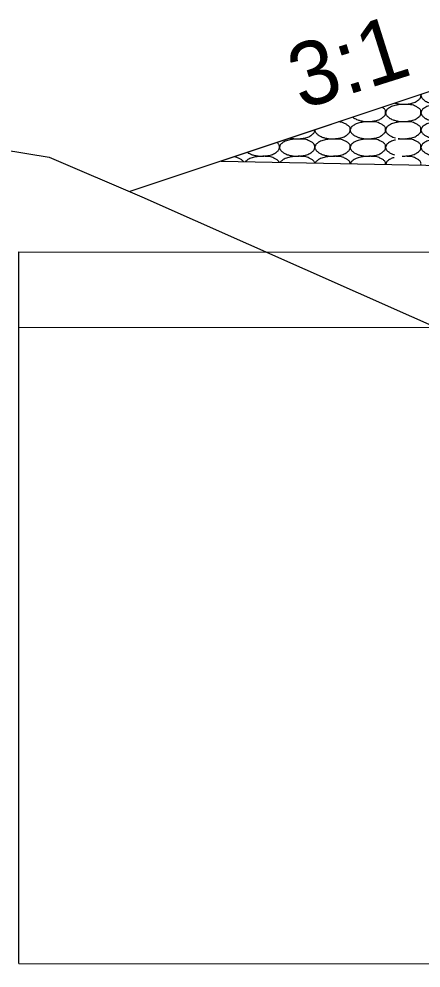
# Model space of a CAD drawing. Extents: x 2829243 to 2838161, y 467639 to 474695.
# Drawn here: x 2830390.5 to 2830428.5, y 467720.8 to 467810.3 of the extents above; entities that cross this region are included whole.
import ezdxf

# ---------------------------------------------------------------- set-up
doc = ezdxf.new("R2010")
doc.units = 0
for name, color, linetype in [('R_Draft', 7, 'Continuous'), ('R_Exist Surface', 7, 'Continuous'), ('R_Water', 7, 'Continuous')]:
    doc.layers.add(name, color=color, linetype=linetype)

msp = doc.modelspace()

# ---------------------------------------------------------------- linework, layer by layer
at = {"layer": 'R_Draft'}
for p, q in [((2830435.568, 467805.556), (2830409.614, 467796.905)), ((2830409.614, 467796.905), (2830674.829, 467791.601))]:
    msp.add_line(p, q, dxfattribs=at)
for points in [[(2830428.513, 467803.204), (2830428.511, 467803.2), (2830428.499, 467803.153), (2830428.456, 467803.078), (2830428.506, 467802.96), (2830428.554, 467802.853), (2830428.649, 467802.736), (2830428.772, 467802.663), (2830428.849, 467802.547), (2830428.983, 467802.521), (2830429.155, 467802.419), (2830429.466, 467802.337), (2830429.868, 467802.253), (2830430.342, 467802.26), (2830430.834, 467802.327), (2830431.282, 467802.448), (2830431.578, 467802.679), (2830431.788, 467802.859), (2830431.812, 467803.052), (2830431.815, 467803.219), (2830431.776, 467803.36), (2830431.694, 467803.457), (2830431.606, 467803.538), (2830431.476, 467803.595), (2830431.365, 467803.686), (2830431.202, 467803.745), (2830431.001, 467803.844), (2830430.754, 467803.857), (2830430.589, 467803.872), (2830430.529, 467803.876)], [(2830426.007, 467802.369), (2830426.031, 467802.363), (2830426.205, 467802.321), (2830426.529, 467802.253), (2830427.003, 467802.26), (2830427.495, 467802.327), (2830427.943, 467802.448), (2830428.239, 467802.679), (2830428.449, 467802.859), (2830428.471, 467803.046), (2830428.476, 467803.148), (2830428.472, 467803.191)], [(2830422.05, 467801.05), (2830422.067, 467801.037), (2830422.118, 467801.002), (2830422.171, 467800.916), (2830422.305, 467800.89), (2830422.476, 467800.788), (2830422.788, 467800.706), (2830423.19, 467800.622), (2830423.664, 467800.629), (2830424.155, 467800.696), (2830424.604, 467800.817), (2830424.9, 467801.048), (2830425.11, 467801.228), (2830425.133, 467801.422), (2830425.137, 467801.588), (2830425.097, 467801.729), (2830425.015, 467801.826), (2830424.927, 467801.907), (2830424.85, 467801.946), (2830424.811, 467801.97)], [(2830425.27, 467801.771), (2830425.239, 467801.744), (2830425.201, 467801.668), (2830425.169, 467801.551), (2830425.116, 467801.447), (2830425.167, 467801.329), (2830425.214, 467801.222), (2830425.31, 467801.105), (2830425.432, 467801.032), (2830425.51, 467800.916), (2830425.644, 467800.89), (2830425.816, 467800.788), (2830426.127, 467800.706), (2830426.529, 467800.622), (2830427.003, 467800.629), (2830427.495, 467800.696), (2830427.943, 467800.817), (2830428.239, 467801.048), (2830428.449, 467801.228), (2830428.472, 467801.422), (2830428.476, 467801.588), (2830428.436, 467801.729), (2830428.354, 467801.826), (2830428.266, 467801.907), (2830428.136, 467801.964), (2830428.025, 467802.055), (2830427.863, 467802.114), (2830427.661, 467802.213), (2830427.331, 467802.234), (2830426.98, 467802.257), (2830426.627, 467802.225), (2830426.355, 467802.221), (2830426.12, 467802.155), (2830425.894, 467802.118), (2830425.678, 467802.041), (2830425.482, 467801.934), (2830425.352, 467801.83), (2830425.262, 467801.77), (2830425.24, 467801.741)], [(2830428.609, 467801.771), (2830428.578, 467801.744), (2830428.54, 467801.668), (2830428.508, 467801.551), (2830428.456, 467801.447), (2830428.506, 467801.329), (2830428.554, 467801.222), (2830428.649, 467801.105), (2830428.772, 467801.032), (2830428.849, 467800.916), (2830428.983, 467800.89), (2830429.155, 467800.788), (2830429.466, 467800.706), (2830429.868, 467800.622), (2830430.342, 467800.629), (2830430.834, 467800.696), (2830431.282, 467800.817), (2830431.578, 467801.048), (2830431.788, 467801.228), (2830431.812, 467801.422), (2830431.815, 467801.588), (2830431.776, 467801.729), (2830431.694, 467801.826), (2830431.606, 467801.907), (2830431.476, 467801.964), (2830431.365, 467802.055), (2830431.202, 467802.114), (2830431.001, 467802.213), (2830430.67, 467802.234), (2830430.319, 467802.257), (2830429.966, 467802.225), (2830429.694, 467802.221), (2830429.46, 467802.155), (2830429.233, 467802.118), (2830429.017, 467802.041), (2830428.821, 467801.934), (2830428.691, 467801.83), (2830428.602, 467801.77), (2830428.579, 467801.741)], [(2830418.472, 467799.857), (2830418.467, 467799.838), (2830418.449, 467799.792), (2830418.489, 467799.698), (2830418.536, 467799.591), (2830418.631, 467799.474), (2830418.754, 467799.401), (2830418.831, 467799.285), (2830418.966, 467799.26), (2830419.137, 467799.157), (2830419.448, 467799.075), (2830419.851, 467798.991), (2830420.325, 467798.999), (2830420.816, 467799.065), (2830421.265, 467799.186), (2830421.561, 467799.418), (2830421.77, 467799.597), (2830421.794, 467799.791), (2830421.797, 467799.957), (2830421.758, 467800.098), (2830421.676, 467800.195), (2830421.588, 467800.276), (2830421.458, 467800.333), (2830421.347, 467800.424), (2830421.185, 467800.483), (2830420.984, 467800.581), (2830420.8, 467800.59), (2830420.697, 467800.599)], [(2830421.931, 467800.14), (2830421.9, 467800.113), (2830421.861, 467800.037), (2830421.829, 467799.92), (2830421.777, 467799.816), (2830421.828, 467799.698), (2830421.875, 467799.591), (2830421.97, 467799.474), (2830422.093, 467799.401), (2830422.171, 467799.285), (2830422.305, 467799.26), (2830422.476, 467799.157), (2830422.788, 467799.075), (2830423.19, 467798.991), (2830423.664, 467798.999), (2830424.155, 467799.065), (2830424.604, 467799.186), (2830424.9, 467799.418), (2830425.11, 467799.597), (2830425.133, 467799.791), (2830425.137, 467799.957), (2830425.097, 467800.098), (2830425.015, 467800.195), (2830424.927, 467800.276), (2830424.797, 467800.333), (2830424.686, 467800.424), (2830424.524, 467800.483), (2830424.322, 467800.582), (2830423.992, 467800.603), (2830423.64, 467800.626), (2830423.287, 467800.594), (2830423.016, 467800.59), (2830422.781, 467800.524), (2830422.554, 467800.487), (2830422.338, 467800.41), (2830422.143, 467800.303), (2830422.013, 467800.199), (2830421.923, 467800.139), (2830421.901, 467800.11)], [(2830426.312, 467799.041), (2830426.384, 467799.027), (2830426.609, 467798.993), (2830427.003, 467798.999), (2830427.495, 467799.065), (2830427.943, 467799.186), (2830428.239, 467799.418), (2830428.449, 467799.597), (2830428.472, 467799.791), (2830428.476, 467799.957), (2830428.436, 467800.098), (2830428.354, 467800.195), (2830428.266, 467800.276), (2830428.136, 467800.333), (2830428.025, 467800.424), (2830427.863, 467800.483), (2830427.661, 467800.582), (2830427.331, 467800.603), (2830426.98, 467800.626), (2830426.627, 467800.594), (2830426.355, 467800.59), (2830426.12, 467800.524), (2830425.894, 467800.487), (2830425.678, 467800.41), (2830425.482, 467800.303), (2830425.352, 467800.199), (2830425.262, 467800.139), (2830425.24, 467800.11)], [(2830428.609, 467800.14), (2830428.578, 467800.113), (2830428.54, 467800.037), (2830428.508, 467799.92), (2830428.456, 467799.816), (2830428.506, 467799.698), (2830428.554, 467799.591), (2830428.649, 467799.474), (2830428.772, 467799.401), (2830428.849, 467799.285), (2830428.983, 467799.26), (2830429.155, 467799.157), (2830429.466, 467799.075), (2830429.868, 467798.991), (2830430.342, 467798.999), (2830430.834, 467799.065), (2830431.282, 467799.186), (2830431.578, 467799.418), (2830431.788, 467799.597), (2830431.812, 467799.791), (2830431.815, 467799.957), (2830431.776, 467800.098), (2830431.694, 467800.195), (2830431.606, 467800.276), (2830431.476, 467800.333), (2830431.365, 467800.424), (2830431.202, 467800.483), (2830431.001, 467800.582), (2830430.67, 467800.603), (2830430.319, 467800.626), (2830429.966, 467800.594), (2830429.694, 467800.59), (2830429.46, 467800.524), (2830429.233, 467800.487), (2830429.017, 467800.41), (2830428.821, 467800.303), (2830428.691, 467800.199), (2830428.602, 467800.139), (2830428.579, 467800.11)], [(2830416.125, 467799.075), (2830416.253, 467799.046), (2830416.533, 467798.991), (2830416.985, 467798.999), (2830417.477, 467799.065), (2830417.925, 467799.186), (2830418.221, 467799.418), (2830418.431, 467799.597), (2830418.449, 467799.759), (2830418.455, 467799.835), (2830418.456, 467799.852)], [(2830425.27, 467800.14), (2830425.239, 467800.113), (2830425.201, 467800.037), (2830425.169, 467799.92), (2830425.116, 467799.816), (2830425.167, 467799.698), (2830425.214, 467799.591), (2830425.31, 467799.474), (2830425.432, 467799.401), (2830425.51, 467799.285), (2830425.644, 467799.26), (2830425.815, 467799.157), (2830425.975, 467799.114), (2830426.077, 467799.09)], [(2830415.252, 467798.509), (2830415.221, 467798.482), (2830415.183, 467798.406), (2830415.151, 467798.289), (2830415.099, 467798.185), (2830415.149, 467798.067), (2830415.196, 467797.96), (2830415.292, 467797.843), (2830415.415, 467797.77), (2830415.492, 467797.654), (2830415.626, 467797.629), (2830415.798, 467797.526), (2830416.109, 467797.444), (2830416.511, 467797.36), (2830416.985, 467797.368), (2830417.477, 467797.434), (2830417.925, 467797.555), (2830418.221, 467797.787), (2830418.431, 467797.966), (2830418.455, 467798.16), (2830418.458, 467798.326), (2830418.419, 467798.467), (2830418.337, 467798.564), (2830418.249, 467798.645), (2830418.119, 467798.702), (2830418.008, 467798.793), (2830417.845, 467798.852), (2830417.644, 467798.951), (2830417.313, 467798.972), (2830416.962, 467798.995), (2830416.609, 467798.963), (2830416.337, 467798.959), (2830416.103, 467798.893), (2830415.876, 467798.856), (2830415.66, 467798.779), (2830415.464, 467798.672), (2830415.334, 467798.568), (2830415.245, 467798.508), (2830415.222, 467798.479)], [(2830418.591, 467798.509), (2830418.56, 467798.482), (2830418.522, 467798.406), (2830418.49, 467798.289), (2830418.438, 467798.185), (2830418.489, 467798.067), (2830418.536, 467797.96), (2830418.631, 467797.843), (2830418.754, 467797.77), (2830418.831, 467797.654), (2830418.966, 467797.629), (2830419.137, 467797.526), (2830419.448, 467797.444), (2830419.851, 467797.36), (2830420.325, 467797.368), (2830420.816, 467797.434), (2830421.265, 467797.555), (2830421.561, 467797.787), (2830421.77, 467797.966), (2830421.794, 467798.16), (2830421.797, 467798.326), (2830421.758, 467798.467), (2830421.676, 467798.564), (2830421.588, 467798.645), (2830421.458, 467798.702), (2830421.347, 467798.793), (2830421.185, 467798.852), (2830420.983, 467798.951), (2830420.653, 467798.972), (2830420.301, 467798.995), (2830419.948, 467798.963), (2830419.676, 467798.959), (2830419.442, 467798.893), (2830419.215, 467798.856), (2830418.999, 467798.779), (2830418.803, 467798.672), (2830418.673, 467798.568), (2830418.584, 467798.508), (2830418.561, 467798.479)], [(2830421.931, 467798.509), (2830421.9, 467798.482), (2830421.861, 467798.406), (2830421.829, 467798.289), (2830421.777, 467798.185), (2830421.828, 467798.067), (2830421.875, 467797.96), (2830421.97, 467797.843), (2830422.093, 467797.77), (2830422.171, 467797.654), (2830422.305, 467797.629), (2830422.476, 467797.526), (2830422.788, 467797.444), (2830423.19, 467797.36), (2830423.664, 467797.368), (2830424.155, 467797.434), (2830424.604, 467797.555), (2830424.9, 467797.787), (2830425.11, 467797.966), (2830425.133, 467798.16), (2830425.137, 467798.326), (2830425.097, 467798.467), (2830425.015, 467798.564), (2830424.927, 467798.645), (2830424.797, 467798.702), (2830424.686, 467798.793), (2830424.524, 467798.852), (2830424.322, 467798.951), (2830423.992, 467798.972), (2830423.64, 467798.995), (2830423.287, 467798.963), (2830423.016, 467798.959), (2830422.781, 467798.893), (2830422.554, 467798.856), (2830422.338, 467798.779), (2830422.143, 467798.672), (2830422.013, 467798.568), (2830421.923, 467798.508), (2830421.901, 467798.479)], [(2830426.062, 467798.882), (2830426.011, 467798.871), (2830425.869, 467798.847), (2830425.678, 467798.779), (2830425.482, 467798.672), (2830425.352, 467798.568), (2830425.262, 467798.508), (2830425.24, 467798.479)], [(2830426.697, 467797.369), (2830426.795, 467797.368), (2830427.058, 467797.376), (2830427.495, 467797.434), (2830427.943, 467797.555), (2830428.239, 467797.787), (2830428.449, 467797.966), (2830428.472, 467798.16), (2830428.476, 467798.326), (2830428.436, 467798.467), (2830428.354, 467798.564), (2830428.266, 467798.645), (2830428.136, 467798.702), (2830428.025, 467798.793), (2830427.863, 467798.852), (2830427.661, 467798.951), (2830427.331, 467798.972), (2830426.98, 467798.995), (2830426.635, 467798.964), (2830426.432, 467798.958), (2830426.335, 467798.943)], [(2830428.609, 467798.509), (2830428.578, 467798.482), (2830428.54, 467798.406), (2830428.508, 467798.289), (2830428.456, 467798.185), (2830428.506, 467798.067), (2830428.554, 467797.96), (2830428.649, 467797.843), (2830428.772, 467797.77), (2830428.849, 467797.654), (2830428.983, 467797.629), (2830429.155, 467797.526), (2830429.466, 467797.444), (2830429.868, 467797.36), (2830430.342, 467797.368), (2830430.834, 467797.434), (2830431.282, 467797.555), (2830431.578, 467797.787), (2830431.788, 467797.966), (2830431.812, 467798.16), (2830431.815, 467798.326), (2830431.776, 467798.467), (2830431.694, 467798.564), (2830431.606, 467798.645), (2830431.476, 467798.702), (2830431.365, 467798.793), (2830431.202, 467798.852), (2830431.001, 467798.951), (2830430.67, 467798.972), (2830430.319, 467798.995), (2830429.966, 467798.963), (2830429.694, 467798.959), (2830429.46, 467798.893), (2830429.233, 467798.856), (2830429.017, 467798.779), (2830428.821, 467798.672), (2830428.691, 467798.568), (2830428.602, 467798.508), (2830428.579, 467798.479)], [(2830412.1, 467797.734), (2830412.124, 467797.712), (2830412.161, 467797.654), (2830412.287, 467797.629), (2830412.459, 467797.526), (2830412.77, 467797.444), (2830413.172, 467797.36), (2830413.646, 467797.368), (2830414.137, 467797.434), (2830414.586, 467797.555), (2830414.882, 467797.787), (2830415.092, 467797.966), (2830415.115, 467798.16), (2830415.119, 467798.326), (2830415.079, 467798.467), (2830414.997, 467798.564), (2830414.936, 467798.625), (2830414.89, 467798.653), (2830414.878, 467798.66)], [(2830425.27, 467798.509), (2830425.239, 467798.482), (2830425.201, 467798.406), (2830425.169, 467798.289), (2830425.116, 467798.185), (2830425.167, 467798.067), (2830425.214, 467797.96), (2830425.31, 467797.843), (2830425.432, 467797.77), (2830425.51, 467797.654), (2830425.644, 467797.629), (2830425.779, 467797.544), (2830425.9, 467797.505), (2830425.962, 467797.488)], [(2830411.715, 467796.863), (2830411.7, 467796.887), (2830411.654, 467796.937), (2830411.57, 467797.014), (2830411.44, 467797.071), (2830411.329, 467797.162), (2830411.167, 467797.221), (2830411.018, 467797.286), (2830410.9, 467797.312), (2830410.856, 467797.319)], [(2830415.087, 467796.795), (2830415.08, 467796.813), (2830415.057, 467796.864), (2830414.997, 467796.933), (2830414.909, 467797.014), (2830414.779, 467797.071), (2830414.668, 467797.162), (2830414.506, 467797.221), (2830414.304, 467797.32), (2830413.974, 467797.341), (2830413.623, 467797.364), (2830413.27, 467797.332), (2830412.998, 467797.328), (2830412.763, 467797.262), (2830412.537, 467797.225), (2830412.321, 467797.148), (2830412.125, 467797.041), (2830411.999, 467796.94), (2830411.913, 467796.882), (2830411.893, 467796.859)], [(2830418.445, 467796.728), (2830418.437, 467796.769), (2830418.41, 467796.847), (2830418.337, 467796.933), (2830418.249, 467797.014), (2830418.119, 467797.071), (2830418.008, 467797.162), (2830417.845, 467797.221), (2830417.644, 467797.32), (2830417.313, 467797.341), (2830416.962, 467797.364), (2830416.609, 467797.332), (2830416.337, 467797.328), (2830416.103, 467797.262), (2830415.876, 467797.225), (2830415.66, 467797.148), (2830415.464, 467797.041), (2830415.334, 467796.937), (2830415.245, 467796.877), (2830415.222, 467796.848)], [(2830421.794, 467796.661), (2830421.793, 467796.67), (2830421.786, 467796.735), (2830421.758, 467796.836), (2830421.676, 467796.933), (2830421.588, 467797.014), (2830421.458, 467797.071), (2830421.347, 467797.162), (2830421.185, 467797.221), (2830420.983, 467797.32), (2830420.653, 467797.341), (2830420.301, 467797.364), (2830419.948, 467797.332), (2830419.676, 467797.328), (2830419.442, 467797.262), (2830419.215, 467797.225), (2830418.999, 467797.148), (2830418.803, 467797.041), (2830418.673, 467796.937), (2830418.584, 467796.877), (2830418.561, 467796.848)], [(2830425.134, 467796.594), (2830425.135, 467796.626), (2830425.132, 467796.714), (2830425.097, 467796.836), (2830425.015, 467796.933), (2830424.927, 467797.014), (2830424.797, 467797.071), (2830424.686, 467797.162), (2830424.524, 467797.221), (2830424.322, 467797.32), (2830423.992, 467797.341), (2830423.64, 467797.364), (2830423.287, 467797.332), (2830423.016, 467797.328), (2830422.781, 467797.262), (2830422.554, 467797.225), (2830422.338, 467797.148), (2830422.143, 467797.041), (2830422.013, 467796.937), (2830421.923, 467796.877), (2830421.901, 467796.848)], [(2830425.943, 467797.225), (2830425.932, 467797.223), (2830425.831, 467797.201), (2830425.678, 467797.148), (2830425.482, 467797.041), (2830425.352, 467796.937), (2830425.262, 467796.877), (2830425.24, 467796.848)], [(2830428.469, 467796.528), (2830428.469, 467796.531), (2830428.474, 467796.584), (2830428.476, 467796.696), (2830428.436, 467796.836), (2830428.354, 467796.933), (2830428.266, 467797.014), (2830428.136, 467797.071), (2830428.025, 467797.162), (2830427.863, 467797.221), (2830427.661, 467797.32), (2830427.331, 467797.341), (2830427.004, 467797.364), (2830426.782, 467797.349), (2830426.703, 467797.343)], [(2830411.913, 467796.878), (2830411.906, 467796.872), (2830411.9, 467796.866), (2830411.894, 467796.859)], [(2830415.252, 467796.878), (2830415.228, 467796.856), (2830415.207, 467796.826), (2830415.192, 467796.793)], [(2830418.591, 467796.878), (2830418.56, 467796.851), (2830418.53, 467796.795), (2830418.512, 467796.741), (2830418.508, 467796.727)], [(2830421.931, 467796.878), (2830421.9, 467796.851), (2830421.861, 467796.775), (2830421.839, 467796.699), (2830421.829, 467796.663), (2830421.829, 467796.661)], [(2830425.27, 467796.878), (2830425.239, 467796.851), (2830425.201, 467796.775), (2830425.173, 467796.677), (2830425.156, 467796.619), (2830425.15, 467796.594)]]:
    msp.add_open_spline(points, degree=3, dxfattribs=at)
at = {"layer": 'R_Exist Surface'}
msp.add_lwpolyline([(2830131.041, 467799.437), (2830153.598, 467802.835), (2830212.638, 467803.951), (2830250.709, 467804.943), (2830331.245, 467803.889), (2830352.705, 467803.588), (2830380.143, 467799.448), (2830393.398, 467797.271), (2830402.14, 467793.537), (2830478.481, 467759.683), (2830503.997, 467759.783), (2830581.42, 467759.793), (2830615.16, 467757.938), (2830740.124, 467755.319), (2830811.852, 467755.014), (2830862.119, 467752.763), (2830887.416, 467744.442), (2830914.475, 467735.817), (2830939.252, 467732.975), (2830981.601, 467728.896), (2831040.287, 467722.845)], dxfattribs=at)
at = {"layer": 'R_Water'}
for p, q in [((2830435.562, 467805.556), (2830400.988, 467794.029)), ((2830390.539, 467788.343), (2830677.804, 467788.104)), ((2830390.539, 467721.26), (2830390.539, 467788.343)), ((2830390.539, 467781.26), (2830687.804, 467781.012)), ((2830390.539, 467721.26), (2830887.093, 467720.846))]:
    msp.add_line(p, q, dxfattribs=at)

# ---------------------------------------------------------------- texts
at = {"layer": 'R_Draft'}
msp.add_text('3:1', height=6, rotation=17.55611, dxfattribs=at).set_placement((2830417.158, 467801.737))

doc.saveas('drawing.dxf')
